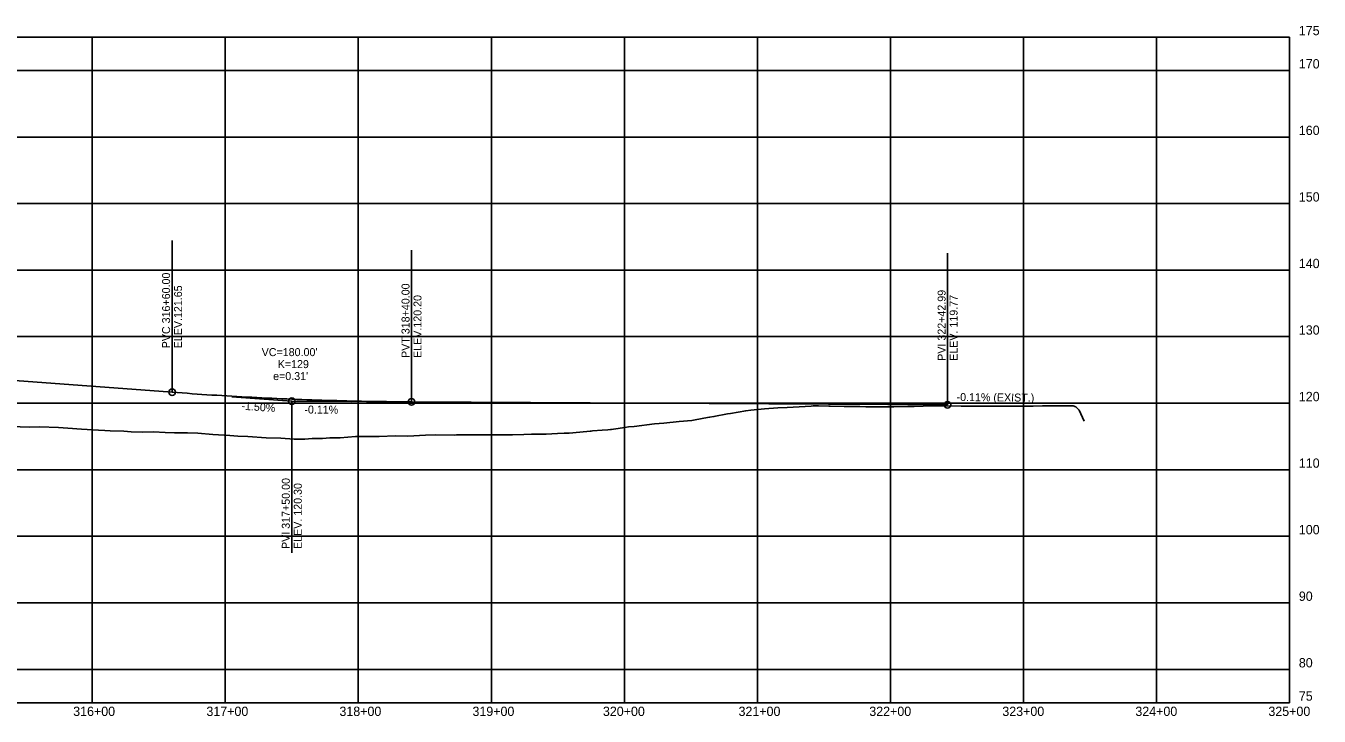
# Model space of a CAD drawing. Extents: x 1191541 to 1200065, y 1475807 to 1480451.
# Drawn here: x 1195456 to 1196429, y 1479932 to 1480451 of the extents above; entities that cross this region are included whole.
import ezdxf

# ---------------------------------------------------------------- set-up
doc = ezdxf.new("R2010")
doc.units = 0
for name, color, linetype in [('R_Exist Surface', 7, 'Continuous'), ('R_Grid', 7, 'Continuous'), ('R_Proposed Const Limits_Hand', 7, 'Continuous'), ('R_Vert Alg', 7, 'Continuous'), ('R_Vert Alg Annot', 7, 'Continuous'), ('R_Water', 7, 'Continuous')]:
    doc.layers.add(name, color=color, linetype=linetype)

msp = doc.modelspace()

# ---------------------------------------------------------------- linework, layer by layer
at = {"layer": 'R_Exist Surface'}
msp.add_lwpolyline([(1195445.01, 1480149.95), (1195459.12, 1480149.58), (1195466.79, 1480149.68), (1195480.91, 1480149.33), (1195488.01, 1480148.85), (1195498.33, 1480148.13), (1195510.95, 1480147.26), (1195515.7, 1480146.94), (1195519.91, 1480146.67), (1195530.03, 1480146.45), (1195535.49, 1480146.08), (1195544.27, 1480145.85), (1195552.45, 1480145.91), (1195561.01, 1480145.54), (1195568.13, 1480145.24), (1195577.86, 1480145.35), (1195585.62, 1480144.94), (1195596.89, 1480144.12), (1195609.77, 1480143.17), (1195615.83, 1480142.85), (1195623.2, 1480142.62), (1195637.12, 1480141.39), (1195648.17, 1480141.17), (1195658.14, 1480140.39), (1195666.12, 1480140.39), (1195671.6, 1480140.9), (1195679.39, 1480140.93), (1195685.04, 1480141.45), (1195692.66, 1480141.5), (1195698.48, 1480142.03), (1195704.13, 1480142.55), (1195711.9, 1480142.63), (1195721.9, 1480142.39), (1195734.38, 1480143.05), (1195743.58, 1480142.82), (1195756.92, 1480143.61), (1195764.6, 1480143.82), (1195778.69, 1480143.62), (1195780.11, 1480143.66), (1195786.6, 1480143.84), (1195788.54, 1480143.82), (1195796.97, 1480143.79), (1195800.48, 1480143.79), (1195805.4, 1480143.72), (1195807.96, 1480143.7), (1195813.83, 1480143.75), (1195821.14, 1480143.85), (1195822.26, 1480143.87), (1195830.69, 1480144.04), (1195836.58, 1480144.19), (1195839.12, 1480144.21), (1195841.71, 1480144.26), (1195845.97, 1480144.19), (1195847.55, 1480144.27), (1195855.98, 1480144.78), (1195861.12, 1480145.13), (1195864.41, 1480145.11), (1195864.78, 1480145.11), (1195872.84, 1480145.74), (1195880.66, 1480146.4), (1195881.27, 1480146.53), (1195882.46, 1480146.8), (1195889.7, 1480147.26), (1195893.98, 1480147.55), (1195895.99, 1480147.84), (1195896.56, 1480147.89), (1195898.13, 1480148.09), (1195906.56, 1480149.25), (1195909.52, 1480149.67), (1195913.58, 1480150.03), (1195929.09, 1480151.91), (1195935.93, 1480152.45), (1195947.58, 1480153.79), (1195957.02, 1480154.46), (1195966.13, 1480156.21), (1195970.39, 1480156.94), (1195973.57, 1480157.49), (1195983.92, 1480159.55), (1195986.21, 1480159.84), (1195997.51, 1480161.83), (1196001.33, 1480162.24), (1196011.69, 1480163.38), (1196021.67, 1480163.95), (1196028.67, 1480164.32), (1196046.71, 1480165.37), (1196048.33, 1480165.45), (1196052.15, 1480165.55), (1196059.89, 1480165.36), (1196061.08, 1480165.35), (1196071.53, 1480165.12), (1196074.43, 1480165.11), (1196083.25, 1480164.93), (1196087.8, 1480164.92), (1196095.03, 1480164.79), (1196101.18, 1480164.8), (1196108.86, 1480164.83), (1196119.5, 1480165.09), (1196124.08, 1480165.12), (1196137.76, 1480165.51), (1196139.35, 1480165.54), (1196146.52, 1480165.55), (1196159.43, 1480165.43), (1196160.99, 1480165.41), (1196179.82, 1480165.23), (1196183.87, 1480165.19), (1196187.48, 1480165.23), (1196198.79, 1480165.29), (1196204.08, 1480165.33), (1196213.73, 1480165.39), (1196220.66, 1480165.45), (1196228.7, 1480165.5), (1196237.24, 1480165.58), (1196243.68, 1480165.62), (1196245.63, 1480164.86), (1196246.55, 1480164), (1196248.25, 1480162.41), (1196251.96, 1480153.97)], dxfattribs=at)
at = {"layer": 'R_Grid'}
for p, q in [((1193906.32, 1480442.53), (1196406.32, 1480442.53)), ((1195506.32, 1479942.53), (1195506.32, 1480442.53)), ((1195606.32, 1479942.53), (1195606.32, 1480442.53)), ((1195706.32, 1479942.53), (1195706.32, 1480442.53)), ((1195806.32, 1479942.53), (1195806.32, 1480442.53)), ((1195906.32, 1479942.53), (1195906.32, 1480442.53)), ((1196006.32, 1479942.53), (1196006.32, 1480442.53)), ((1196106.32, 1479942.53), (1196106.32, 1480442.53)), ((1196206.32, 1479942.53), (1196206.32, 1480442.53)), ((1196306.32, 1479942.53), (1196306.32, 1480442.53)), ((1193906.32, 1480417.53), (1196406.32, 1480417.53)), ((1193906.32, 1480367.53), (1196406.32, 1480367.53)), ((1193906.32, 1480317.53), (1196406.32, 1480317.53)), ((1193906.32, 1480267.53), (1196406.32, 1480267.53)), ((1193906.32, 1480217.53), (1196406.32, 1480217.53)), ((1193906.32, 1480167.53), (1196406.32, 1480167.53)), ((1193906.32, 1480117.53), (1196406.32, 1480117.53)), ((1193906.32, 1480067.53), (1196406.32, 1480067.53)), ((1193906.32, 1480017.53), (1196406.32, 1480017.53)), ((1193906.32, 1479967.53), (1196406.32, 1479967.53))]:
    msp.add_line(p, q, dxfattribs=at)
at = {"layer": 'R_Vert Alg'}
for p, q in [((1195397.1, 1480188.48), (1195566.32, 1480175.77)), ((1195611.32, 1480172.39), (1195656.32, 1480169.01)), ((1195656.32, 1480169.01), (1195701.32, 1480168.77)), ((1195746.32, 1480168.53), (1196149.31, 1480166.38))]:
    msp.add_line(p, q, dxfattribs=at)
msp.add_lwpolyline([(1195566.32, 1480175.77), (1195570.07, 1480175.49), (1195573.82, 1480175.21), (1195577.57, 1480174.95), (1195581.32, 1480174.68), (1195585.07, 1480174.43), (1195588.82, 1480174.17), (1195592.57, 1480173.93), (1195596.32, 1480173.69), (1195600.07, 1480173.45), (1195603.82, 1480173.22), (1195607.57, 1480173), (1195611.32, 1480172.78), (1195615.07, 1480172.57), (1195618.82, 1480172.36), (1195622.57, 1480172.15), (1195626.32, 1480171.96), (1195630.07, 1480171.77), (1195633.82, 1480171.58), (1195637.57, 1480171.4), (1195641.32, 1480171.22), (1195645.07, 1480171.05), (1195648.82, 1480170.89), (1195652.57, 1480170.73), (1195660.07, 1480170.43), (1195663.82, 1480170.29), (1195667.57, 1480170.15), (1195671.32, 1480170.02), (1195675.07, 1480169.89), (1195678.82, 1480169.77), (1195682.57, 1480169.65), (1195686.32, 1480169.54), (1195690.07, 1480169.44), (1195693.82, 1480169.34), (1195697.57, 1480169.25), (1195701.32, 1480169.16), (1195705.07, 1480169.08), (1195708.82, 1480169), (1195712.57, 1480168.93), (1195716.32, 1480168.86), (1195720.07, 1480168.8), (1195723.82, 1480168.74), (1195727.57, 1480168.69), (1195731.32, 1480168.65), (1195735.07, 1480168.61), (1195738.82, 1480168.58), (1195742.57, 1480168.55), (1195746.32, 1480168.53)], dxfattribs=at)
at = {"layer": 'R_Vert Alg Annot'}
for p, q in [((1195566.32, 1480205.77), (1195566.32, 1480289.77)), ((1195746.32, 1480198.53), (1195746.32, 1480282.53)), ((1196149.31, 1480196.38), (1196149.31, 1480280.38)), ((1195566.32, 1480175.77), (1195566.32, 1480205.77)), ((1195746.32, 1480168.53), (1195746.32, 1480198.53)), ((1196149.31, 1480166.38), (1196149.31, 1480196.38)), ((1195656.32, 1480169.01), (1195656.32, 1480139.01)), ((1195656.32, 1480139.01), (1195656.32, 1480055.01))]:
    msp.add_line(p, q, dxfattribs=at)
for centre in [(1195566.32, 1480175.77), (1195656.32, 1480169.01), (1195746.32, 1480168.53), (1196149.31, 1480166.38)]:
    msp.add_circle(centre, 2.5, dxfattribs=at)
at = {"layer": 'R_Water'}
for p, q in [((1196406.32, 1479942.53), (1196406.32, 1480442.53)), ((1193906.32, 1479942.53), (1196406.32, 1479942.53))]:
    msp.add_line(p, q, dxfattribs=at)

# ---------------------------------------------------------------- texts
at = {"layer": 'R_Proposed Const Limits_Hand'}
for s, p in [('175', (1196413.32, 1480444.03)), ('170', (1196413.32, 1480419.03)), ('160', (1196413.32, 1480369.03)), ('150', (1196413.32, 1480319.03)), ('140', (1196413.32, 1480269.03)), ('130', (1196413.32, 1480219.03)), ('120', (1196413.32, 1480169.03)), ('110', (1196413.32, 1480119.03)), ('100', (1196413.32, 1480069.03)), ('90', (1196413.32, 1480019.03)), ('80', (1196413.32, 1479969.03)), ('75', (1196413.32, 1479944.03)), ('316+00', (1195491.99, 1479932.53)), ('317+00', (1195592.13, 1479932.53)), ('318+00', (1195692.13, 1479932.53)), ('319+00', (1195792.13, 1479932.53)), ('320+00', (1195890.19, 1479932.53)), ('321+00', (1195992.13, 1479932.53)), ('322+00', (1196090.43, 1479932.53)), ('323+00', (1196190.43, 1479932.53)), ('324+00', (1196290.43, 1479932.53)), ('325+00', (1196390.43, 1479932.53))]:
    msp.add_text(s, height=7, dxfattribs=at).set_placement(p)
at = {"layer": 'R_Vert Alg Annot'}
for s, rotation, p in [('PVC 316+60.00', 90, (1195564.82, 1480208.77)), ('ELEV.121.65', 90, (1195573.82, 1480208.77)), ('PVT 318+40.00', 90, (1195744.82, 1480201.53)), ('PVI 322+42.99', 90, (1196147.81, 1480199.38)), ('ELEV.120.20', 90, (1195753.82, 1480201.53)), ('ELEV. 119.77', 90, (1196156.81, 1480199.38)), ('-0.11% (EXIST.)', 359.49633, (1196156.03, 1480169.18)), ('-1.50%', 355.70485, (1195618.3, 1480162.71)), ('-0.11%', 359.69432, (1195665.77, 1480159.78)), ('PVI 317+50.00', 90, (1195654.82, 1480058.01)), ('ELEV. 120.30', 90, (1195663.82, 1480058.01))]:
    msp.add_text(s, height=6, rotation=rotation, dxfattribs=at).set_placement(p)
for s, p in [("VC=180.00'", (1195633.69, 1480202.91)), ('K=129', (1195645.76, 1480193.91)), ("e=0.31'", (1195642.29, 1480184.91))]:
    msp.add_text(s, height=6, dxfattribs=at).set_placement(p)

doc.saveas('drawing.dxf')
